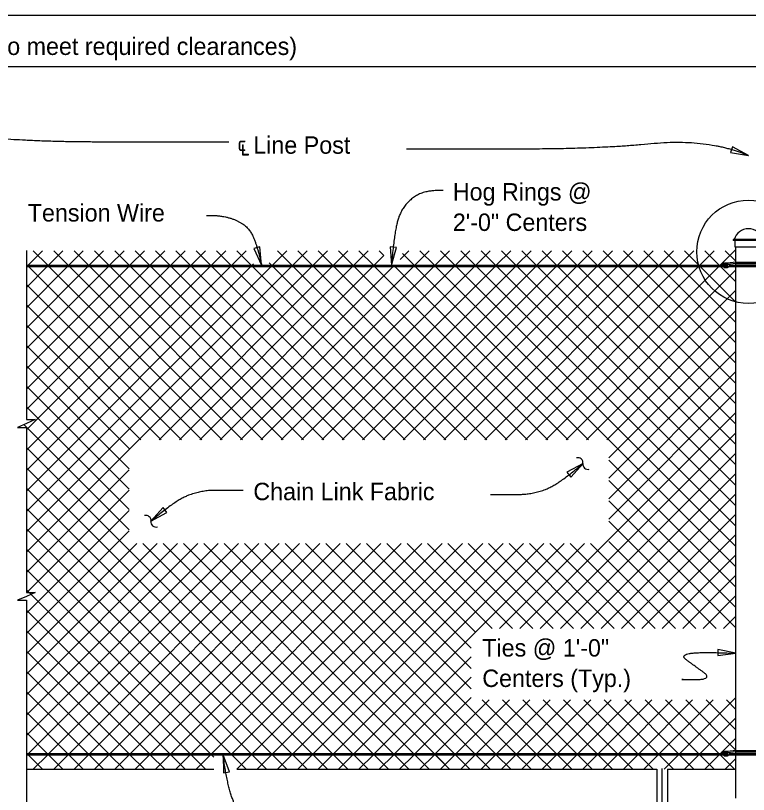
# Model space of a CAD drawing. Extents: x 0 to 72.1, y -15.2 to 30.1.
# Drawn here: x 16.14 to 24.63, y 18.99 to 28 of the extents above; entities that cross this region are included whole.
import ezdxf

# ---------------------------------------------------------------- set-up
doc = ezdxf.new("R2010")
doc.units = 0
for name, color, linetype in [('ActivePts-ConstElements', 7, 'Continuous'), ('AdhocPoint_dp', 7, 'Continuous'), ('Border', 7, 'Continuous'), ('Patterning', 7, 'Continuous'), ('PlotBorder_dp', 7, 'Continuous'), ('SheetBorder_dp', 7, 'Continuous'), ('SheetLines_dp', 7, 'Continuous'), ('TextMisc', 7, 'Continuous')]:
    doc.layers.add(name, color=color, linetype=linetype)

msp = doc.modelspace()

# ---------------------------------------------------------------- linework, layer by layer
at = {"layer": 'ActivePts-ConstElements'}
msp.add_lwpolyline([(0.016, 2.0538), (41.0666, 2.0538), (41.0666, 27.9999), (0.016, 27.9999)], close=True, dxfattribs=at)
at = {"layer": 'AdhocPoint_dp'}
for p, q in [((16.268, 19.2783), (18.44, 19.2783)), ((18.704, 19.2783), (23.5698, 19.2783)), ((23.5698, 19.2783), (23.5698, 14.757)), ((23.6923, 19.2783), (23.6923, 15.6116)), ((23.6923, 19.2783), (24.4852, 19.2783))]:
    msp.add_line(p, q, dxfattribs=at)
at = {"layer": 'Border'}
for p, q in [((24.4852, 25.1116), (24.7769, 25.1116)), ((24.4852, 25.0969), (24.7769, 25.0969)), ((24.4852, 19.4597), (24.7769, 19.4597)), ((24.4852, 19.445), (24.7769, 19.445))]:
    msp.add_line(p, q, dxfattribs=at)
at = {"layer": 'Patterning'}
for p, q in [((16.2896, 25.1116), (16.4562, 25.2783)), ((16.3488, 25.2783), (16.5155, 25.1116)), ((16.5253, 25.1116), (16.6919, 25.2783)), ((16.5845, 25.2783), (16.7512, 25.1116)), ((16.761, 25.1116), (16.9276, 25.2783)), ((16.8202, 25.2783), (16.9869, 25.1116)), ((16.9967, 25.1116), (17.1633, 25.2783)), ((17.0559, 25.2783), (17.2226, 25.1116)), ((17.2324, 25.1116), (17.3991, 25.2783)), ((17.2916, 25.2783), (17.4583, 25.1116)), ((17.4681, 25.1116), (17.6348, 25.2783)), ((17.5273, 25.2783), (17.694, 25.1116)), ((17.7038, 25.1116), (17.8705, 25.2783)), ((17.763, 25.2783), (17.9297, 25.1116)), ((17.9395, 25.1116), (18.1062, 25.2783)), ((17.9987, 25.2783), (18.1654, 25.1116)), ((18.1752, 25.1116), (18.3419, 25.2783)), ((18.2344, 25.2783), (18.4011, 25.1116)), ((18.4109, 25.1116), (18.5776, 25.2783)), ((18.4701, 25.2783), (18.6368, 25.1116)), ((18.6466, 25.1116), (18.8133, 25.2783)), ((18.7058, 25.2783), (18.8725, 25.1116)), ((19.118, 25.1116), (19.2847, 25.2783)), ((19.1772, 25.2783), (19.3439, 25.1116)), ((19.3537, 25.1116), (19.5204, 25.2783)), ((19.4129, 25.2783), (19.5796, 25.1116)), ((19.5894, 25.1116), (19.7561, 25.2783)), ((19.6486, 25.2783), (19.8153, 25.1116)), ((19.8251, 25.1116), (19.9918, 25.2783)), ((19.8843, 25.2783), (20.051, 25.1116)), ((20.0608, 25.1116), (20.2275, 25.2783)), ((20.12, 25.2783), (20.2867, 25.1116)), ((20.3557, 25.2783), (20.4095, 25.2246)), ((20.5989, 25.1783), (20.6989, 25.2783)), ((20.6246, 25.2452), (20.7581, 25.1116)), ((20.7679, 25.1116), (20.9346, 25.2783)), ((20.8271, 25.2783), (20.9938, 25.1116)), ((21.0036, 25.1116), (21.1703, 25.2783)), ((21.0628, 25.2783), (21.2295, 25.1116)), ((21.2393, 25.1116), (21.406, 25.2783)), ((21.2985, 25.2783), (21.4652, 25.1116)), ((21.475, 25.1116), (21.6417, 25.2783)), ((21.5342, 25.2783), (21.7009, 25.1116)), ((21.7107, 25.1116), (21.8774, 25.2783)), ((21.7699, 25.2783), (21.9366, 25.1116)), ((21.9464, 25.1116), (22.1131, 25.2783)), ((22.0057, 25.2783), (22.1723, 25.1116)), ((22.1821, 25.1116), (22.3488, 25.2783)), ((22.2414, 25.2783), (22.408, 25.1116)), ((22.2834, 23.0916), (24.4852, 25.2934)), ((22.4178, 25.1116), (22.5845, 25.2783)), ((22.4771, 25.2783), (22.6437, 25.1116)), ((22.6535, 25.1116), (22.8202, 25.2783)), ((22.7128, 25.2783), (22.8794, 25.1116)), ((22.8892, 25.1116), (23.0559, 25.2783)), ((22.9485, 25.2783), (23.1151, 25.1116)), ((23.1249, 25.1116), (23.2916, 25.2783)), ((23.1842, 25.2783), (23.3508, 25.1116)), ((23.3606, 25.1116), (23.5273, 25.2783)), ((23.4199, 25.2783), (23.5865, 25.1116)), ((23.5963, 25.1116), (23.763, 25.2783)), ((23.6556, 25.2783), (23.8222, 25.1116)), ((23.832, 25.1116), (23.9987, 25.2783)), ((23.8913, 25.2783), (24.0579, 25.1116)), ((24.0677, 25.1116), (24.2344, 25.2783)), ((24.127, 25.2783), (24.2936, 25.1116)), ((24.3035, 25.1116), (24.4701, 25.2783)), ((24.3627, 25.2783), (24.4852, 25.1557)), ((20.2965, 25.1116), (20.4095, 25.2246)), ((16.268, 21.7902), (19.5747, 25.0969)), ((16.268, 22.2616), (19.1033, 25.0969)), ((16.268, 23.2044), (18.1604, 25.0969)), ((16.268, 22.733), (18.6318, 25.0969)), ((16.268, 22.0259), (19.339, 25.0969)), ((16.268, 22.4973), (18.8675, 25.0969)), ((16.268, 22.9687), (18.3961, 25.0969)), ((16.268, 23.4402), (17.9247, 25.0969)), ((16.268, 23.6759), (17.689, 25.0969)), ((16.268, 24.1473), (17.2176, 25.0969)), ((16.268, 23.9116), (17.4533, 25.0969)), ((16.268, 24.6187), (16.7462, 25.0969)), ((16.268, 25.0901), (16.2748, 25.0969)), ((16.268, 24.383), (16.9819, 25.0969)), ((16.268, 24.8544), (16.5105, 25.0969)), ((16.2945, 25.0969), (18.2998, 23.0916)), ((16.5302, 25.0969), (18.5355, 23.0916)), ((16.7659, 25.0969), (18.7712, 23.0916)), ((17.0016, 25.0969), (19.0069, 23.0916)), ((17.2373, 25.0969), (19.2426, 23.0916)), ((17.473, 25.0969), (19.4783, 23.0916)), ((17.7087, 25.0969), (19.714, 23.0916)), ((17.8051, 23.0916), (19.8104, 25.0969)), ((17.9444, 25.0969), (19.9497, 23.0916)), ((18.0408, 23.0916), (20.0461, 25.0969)), ((18.1801, 25.0969), (20.1854, 23.0916)), ((18.2765, 23.0916), (20.2818, 25.0969)), ((18.4158, 25.0969), (20.4211, 23.0916)), ((18.5122, 23.0916), (20.5175, 25.0969)), ((18.6515, 25.0969), (20.6568, 23.0916)), ((18.7479, 23.0916), (20.7532, 25.0969)), ((18.8823, 25.1116), (18.8973, 25.1266)), ((18.8872, 25.0969), (20.8925, 23.0916)), ((18.9836, 23.0916), (20.9889, 25.0969)), ((19.081, 25.1388), (19.1082, 25.1116)), ((19.1229, 25.0969), (21.1282, 23.0916)), ((19.2193, 23.0916), (21.2246, 25.0969)), ((19.3586, 25.0969), (21.3639, 23.0916)), ((19.455, 23.0916), (21.4603, 25.0969)), ((19.5943, 25.0969), (21.5996, 23.0916)), ((19.6907, 23.0916), (21.696, 25.0969)), ((19.83, 25.0969), (21.8353, 23.0916)), ((19.9264, 23.0916), (21.9317, 25.0969)), ((20.0657, 25.0969), (22.071, 23.0916)), ((20.1621, 23.0916), (22.1674, 25.0969)), ((20.3015, 25.0969), (22.3067, 23.0916)), ((20.3978, 23.0916), (22.4031, 25.0969)), ((20.5372, 25.0969), (22.5424, 23.0916)), ((20.6335, 23.0916), (22.6388, 25.0969)), ((20.7729, 25.0969), (22.7781, 23.0916)), ((20.8692, 23.0916), (22.8745, 25.0969)), ((21.0086, 25.0969), (24.4852, 21.6202)), ((21.1049, 23.0916), (23.1102, 25.0969)), ((21.2443, 25.0969), (24.4852, 21.8559)), ((21.3406, 23.0916), (23.3459, 25.0969)), ((21.48, 25.0969), (24.4852, 22.0916)), ((21.5763, 23.0916), (23.5816, 25.0969)), ((21.7157, 25.0969), (24.4852, 22.3273)), ((21.812, 23.0916), (23.8173, 25.0969)), ((21.9514, 25.0969), (24.4852, 22.563)), ((22.0477, 23.0916), (24.053, 25.0969)), ((22.1871, 25.0969), (24.4852, 22.7987)), ((22.4228, 25.0969), (24.4852, 23.0344)), ((22.6585, 25.0969), (24.4852, 23.2701)), ((22.8942, 25.0969), (24.4852, 23.5058)), ((23.1299, 25.0969), (24.4852, 23.7415)), ((23.3656, 25.0969), (24.4852, 23.9772)), ((23.6013, 25.0969), (24.4852, 24.2129)), ((23.837, 25.0969), (24.4852, 24.4486)), ((24.0727, 25.0969), (24.4852, 24.6843)), ((24.3084, 25.0969), (24.4852, 24.92)), ((22.5191, 23.0916), (24.4852, 25.0577)), ((16.268, 24.8877), (18.0641, 23.0916)), ((22.7548, 23.0916), (24.4852, 24.822)), ((16.268, 24.652), (17.8284, 23.0916)), ((22.9905, 23.0916), (24.4852, 24.5863)), ((16.268, 24.4163), (17.5927, 23.0916)), ((23.0145, 22.8799), (24.4852, 24.3506)), ((16.268, 24.1806), (17.4577, 22.9909)), ((23.0145, 22.6442), (24.4852, 24.1149)), ((16.268, 23.9449), (17.4577, 22.7552)), ((23.0145, 22.4085), (24.4852, 23.8792)), ((16.268, 23.7092), (17.4577, 22.5195)), ((23.0145, 22.1728), (24.4852, 23.6435)), ((16.268, 23.4735), (17.4577, 22.2838)), ((21.9837, 20.9063), (24.4852, 23.4078)), ((16.2393, 23.2665), (17.4577, 22.0481)), ((22.2194, 20.9063), (24.4852, 23.1721)), ((16.268, 23.0021), (19.8104, 19.4597)), ((22.4551, 20.9063), (24.4852, 22.9364)), ((23.0145, 22.8552), (24.4852, 21.3845)), ((16.268, 22.7664), (19.5747, 19.4597)), ((16.268, 21.5545), (17.4577, 22.7442)), ((22.6908, 20.9063), (24.4852, 22.7007)), ((23.0145, 22.6195), (24.4852, 21.1488)), ((16.268, 22.5307), (19.339, 19.4597)), ((16.2718, 21.3227), (17.4577, 22.5085)), ((22.9265, 20.9063), (24.4852, 22.465)), ((23.0145, 22.3838), (24.4852, 20.9131)), ((16.268, 22.295), (19.1033, 19.4597)), ((16.268, 21.0831), (17.4577, 22.2728)), ((23.1623, 20.9063), (24.4852, 22.2293)), ((23.0145, 22.1481), (24.2563, 20.9063)), ((16.268, 22.0593), (18.8675, 19.4597)), ((16.268, 20.8474), (17.4577, 22.0371)), ((23.0145, 21.9124), (24.0206, 20.9063)), ((23.398, 20.9063), (24.4852, 21.9936)), ((16.268, 19.9046), (18.2538, 21.8904)), ((16.268, 20.376), (17.7824, 21.8904)), ((16.268, 20.6117), (17.5467, 21.8904)), ((16.268, 20.1403), (18.0181, 21.8904)), ((16.268, 19.6689), (18.4895, 21.8904)), ((16.268, 21.8236), (18.6318, 19.4597)), ((16.2945, 19.4597), (18.7252, 21.8904)), ((16.5302, 19.4597), (18.9609, 21.8904)), ((16.7659, 19.4597), (19.1966, 21.8904)), ((17.0016, 19.4597), (19.4323, 21.8904)), ((17.2373, 19.4597), (19.668, 21.8904)), ((17.473, 19.4597), (19.9037, 21.8904)), ((17.6154, 21.8904), (20.0461, 19.4597)), ((17.7087, 19.4597), (20.1394, 21.8904)), ((17.8511, 21.8904), (20.2818, 19.4597)), ((17.9444, 19.4597), (20.3751, 21.8904)), ((18.0868, 21.8904), (20.5175, 19.4597)), ((18.1801, 19.4597), (20.6108, 21.8904)), ((18.3225, 21.8904), (20.7532, 19.4597)), ((18.4158, 19.4597), (20.8465, 21.8904)), ((18.5582, 21.8904), (21.1067, 19.3419)), ((18.6515, 19.4597), (21.0822, 21.8904)), ((18.7939, 21.8904), (21.2246, 19.4597)), ((18.8872, 19.4597), (21.3179, 21.8904)), ((19.0296, 21.8904), (21.4603, 19.4597)), ((19.1229, 19.4597), (21.5536, 21.8904)), ((19.2653, 21.8904), (21.696, 19.4597)), ((19.3586, 19.4597), (21.7893, 21.8904)), ((19.501, 21.8904), (21.9317, 19.4597)), ((19.5943, 19.4597), (22.025, 21.8904)), ((19.7122, 19.3419), (22.2607, 21.8904)), ((19.7367, 21.8904), (21.42, 20.2072)), ((19.9724, 21.8904), (21.42, 20.4429)), ((20.0657, 19.4597), (22.4964, 21.8904)), ((20.2081, 21.8904), (21.42, 20.6786)), ((20.4438, 21.8904), (21.4701, 20.8641)), ((20.6795, 21.8904), (21.6636, 20.9063)), ((20.9152, 21.8904), (21.8993, 20.9063)), ((21.1509, 21.8904), (22.135, 20.9063)), ((21.3866, 21.8904), (22.3707, 20.9063)), ((21.6223, 21.8904), (22.6064, 20.9063)), ((21.748, 20.9063), (22.7321, 21.8904)), ((21.858, 21.8904), (22.8421, 20.9063)), ((22.0937, 21.8904), (23.0778, 20.9063)), ((22.3294, 21.8904), (23.3135, 20.9063)), ((22.5651, 21.8904), (23.5492, 20.9063)), ((22.8008, 21.8904), (23.7849, 20.9063)), ((23.6337, 20.9063), (24.4852, 21.7579)), ((16.268, 21.5879), (18.3961, 19.4597)), ((23.8694, 20.9063), (24.4852, 21.5222)), ((16.268, 21.3522), (18.1604, 19.4597)), ((24.1051, 20.9063), (24.4852, 21.2865)), ((16.268, 21.1165), (17.9247, 19.4597)), ((24.3408, 20.9063), (24.4852, 21.0508)), ((16.268, 20.8808), (17.689, 19.4597)), ((16.268, 20.6451), (17.4533, 19.4597)), ((20.3015, 19.4597), (21.42, 20.5782)), ((16.268, 20.4094), (17.2176, 19.4597)), ((20.5372, 19.4597), (21.42, 20.3425)), ((16.268, 20.1737), (16.9819, 19.4597)), ((20.7729, 19.4597), (21.42, 20.1068)), ((23.837, 19.4597), (24.4852, 20.108)), ((21.0086, 19.4597), (21.6282, 20.0793)), ((21.2443, 19.4597), (21.8639, 20.0793)), ((21.48, 19.4597), (22.0996, 20.0793)), ((21.5478, 20.0793), (22.1674, 19.4597)), ((21.7157, 19.4597), (22.3353, 20.0793)), ((21.7835, 20.0793), (22.4031, 19.4597)), ((21.9514, 19.4597), (22.571, 20.0793)), ((22.0192, 20.0793), (22.6388, 19.4597)), ((22.1871, 19.4597), (22.8067, 20.0793)), ((22.2549, 20.0793), (22.8745, 19.4597)), ((22.4228, 19.4597), (23.0424, 20.0793)), ((22.4906, 20.0793), (23.1102, 19.4597)), ((22.6585, 19.4597), (23.2781, 20.0793)), ((22.7263, 20.0793), (23.3459, 19.4597)), ((22.8942, 19.4597), (23.5138, 20.0793)), ((22.962, 20.0793), (23.5816, 19.4597)), ((23.1299, 19.4597), (23.7495, 20.0793)), ((23.1977, 20.0793), (23.8173, 19.4597)), ((23.3656, 19.4597), (23.9852, 20.0793)), ((23.4334, 20.0793), (24.053, 19.4597)), ((23.6013, 19.4597), (24.2209, 20.0793)), ((23.6691, 20.0793), (24.2887, 19.4597)), ((23.9048, 20.0793), (24.4852, 19.4989)), ((24.1405, 20.0793), (24.4852, 19.7346)), ((24.3762, 20.0793), (24.4852, 19.9703)), ((16.268, 19.938), (16.7462, 19.4597)), ((24.0727, 19.4597), (24.4852, 19.8723)), ((16.268, 19.7023), (16.5105, 19.4597)), ((24.3243, 19.4757), (24.4852, 19.6366)), ((16.2896, 19.445), (16.4562, 19.2783)), ((16.3488, 19.2783), (16.5155, 19.445)), ((16.5253, 19.445), (16.6919, 19.2783)), ((16.5845, 19.2783), (16.7512, 19.445)), ((16.761, 19.445), (16.9276, 19.2783)), ((16.8202, 19.2783), (16.9869, 19.445)), ((16.9967, 19.445), (17.1633, 19.2783)), ((17.0559, 19.2783), (17.2226, 19.445)), ((17.2324, 19.445), (17.3991, 19.2783)), ((17.2916, 19.2783), (17.4583, 19.445)), ((17.4681, 19.445), (17.6348, 19.2783)), ((17.5273, 19.2783), (17.694, 19.445)), ((17.7038, 19.445), (17.8705, 19.2783)), ((17.763, 19.2783), (17.9297, 19.445)), ((17.9395, 19.445), (18.1062, 19.2783)), ((17.9987, 19.2783), (18.1654, 19.445)), ((18.1752, 19.445), (18.3419, 19.2783)), ((18.2344, 19.2783), (18.4011, 19.445)), ((18.4109, 19.445), (18.44, 19.4159)), ((18.6466, 19.445), (18.8133, 19.2783)), ((18.7058, 19.2783), (18.8725, 19.445)), ((18.8823, 19.445), (19.049, 19.2783)), ((18.9415, 19.2783), (19.1082, 19.445)), ((19.118, 19.445), (19.2847, 19.2783)), ((19.1772, 19.2783), (19.3439, 19.445)), ((19.3537, 19.445), (19.5204, 19.2783)), ((19.4129, 19.2783), (19.5796, 19.445)), ((19.5894, 19.445), (19.7561, 19.2783)), ((19.6486, 19.2783), (19.8153, 19.445)), ((19.8251, 19.445), (19.9918, 19.2783)), ((19.8843, 19.2783), (20.051, 19.445)), ((20.0608, 19.445), (20.2275, 19.2783)), ((20.12, 19.2783), (20.2867, 19.445)), ((20.2965, 19.445), (20.4632, 19.2783)), ((20.3557, 19.2783), (20.5224, 19.445)), ((20.5322, 19.445), (20.6989, 19.2783)), ((20.5914, 19.2783), (20.7581, 19.445)), ((20.7679, 19.445), (20.9346, 19.2783)), ((20.8271, 19.2783), (20.9938, 19.445)), ((21.0036, 19.445), (21.1703, 19.2783)), ((21.0628, 19.2783), (21.2295, 19.445)), ((21.2393, 19.445), (21.406, 19.2783)), ((21.2985, 19.2783), (21.4652, 19.445)), ((21.475, 19.445), (21.6417, 19.2783)), ((21.5342, 19.2783), (21.7009, 19.445)), ((21.7107, 19.445), (21.8774, 19.2783)), ((21.7699, 19.2783), (21.9366, 19.445)), ((21.9464, 19.445), (22.1131, 19.2783)), ((22.0057, 19.2783), (22.1723, 19.445)), ((22.1821, 19.445), (22.3488, 19.2783)), ((22.2414, 19.2783), (22.408, 19.445)), ((22.4178, 19.445), (22.5845, 19.2783)), ((22.4771, 19.2783), (22.6437, 19.445)), ((22.6535, 19.445), (22.8202, 19.2783)), ((22.7128, 19.2783), (22.8794, 19.445)), ((22.8892, 19.445), (23.0559, 19.2783)), ((22.9485, 19.2783), (23.1151, 19.445)), ((23.1249, 19.445), (23.2916, 19.2783)), ((23.1842, 19.2783), (23.3508, 19.445)), ((23.3606, 19.445), (23.5273, 19.2783)), ((23.4199, 19.2783), (23.5865, 19.445)), ((23.5963, 19.445), (23.763, 19.2783)), ((23.6556, 19.2783), (23.8222, 19.445)), ((23.832, 19.445), (23.9987, 19.2783)), ((23.8913, 19.2783), (24.0579, 19.445)), ((24.0677, 19.445), (24.2344, 19.2783)), ((24.127, 19.2783), (24.2936, 19.445)), ((24.3035, 19.445), (24.4701, 19.2783)), ((24.3084, 19.4597), (24.312, 19.4633)), ((24.3627, 19.2783), (24.4852, 19.4009))]:
    msp.add_line(p, q, dxfattribs=at)
at = {"layer": 'PlotBorder_dp'}
for points in [[(13.631, 27.4094), (15.0947, 27.4094), (15.0947, 27.5128), (15.1397, 27.4094), (15.1847, 27.3061), (15.1847, 27.4094), (28.4756, 27.4094)], [(16.268, 25.2804), (16.268, 23.3241), (16.3714, 23.3241), (16.268, 23.2791), (16.1647, 23.2341), (16.268, 23.2341), (16.268, 22.3405)], [(16.268, 22.3405), (16.268, 21.3227), (16.3714, 21.3227), (16.268, 21.2777), (16.1647, 21.2327), (16.268, 21.2327), (16.268, 19.0284)], [(16.268, 19.2784), (16.268, 17.4276), (16.3714, 17.4276), (16.268, 17.3826), (16.1647, 17.3376), (16.268, 17.3376), (16.268, 14.9877)]]:
    msp.add_lwpolyline(points, dxfattribs=at)
for points in [[(24.6311, 26.3822), (24.4447, 26.4815), (24.4224, 26.4146)], [(18.9924, 25.1117), (18.9722, 25.3219), (18.9041, 25.3035)], [(20.4977, 25.1117), (20.5537, 25.3153), (20.4835, 25.3224)], [(22.7151, 22.8151), (22.5295, 22.7141), (22.5731, 22.6586)], [(17.711, 22.1484), (17.8965, 22.2494), (17.8529, 22.3049)], [(24.4853, 20.6199), (24.2786, 20.6637), (24.2757, 20.5932)], [(18.5457, 19.445), (18.5507, 19.2338), (18.6199, 19.2473)]]:
    msp.add_lwpolyline(points, close=True, dxfattribs=at)
msp.add_circle((24.631, 25.2659), 0.5976, dxfattribs=at)
for centre, start, end in [((22.6555, 22.8235), 352.34263, 104.06985), ((22.7736, 22.8076), 172.34263, 284.06985), ((17.6524, 22.1558), 352.34263, 104.06985), ((17.7706, 22.1399), 172.34263, 284.06985)]:
    msp.add_arc(centre, 0.0596, start, end, dxfattribs=at)
for points in [[(18.6126, 26.5365), (17.8093, 26.5365), (16.42, 26.5365), (15.2385, 26.6311), (14.631, 26.7352)], [(20.6722, 26.4584), (21.1189, 26.4584), (22.8863, 26.4584), (24.1529, 26.5814), (24.631, 26.3821)], [(21.0973, 25.9736), (20.8794, 25.986), (20.6356, 25.8115), (20.5295, 25.5276), (20.4977, 25.1116)], [(18.354, 25.687), (18.5344, 25.6941), (18.8173, 25.5843), (18.9376, 25.3648), (18.9924, 25.1116)], [(21.6418, 22.4586), (21.8439, 22.4586), (22.1175, 22.4586), (22.4243, 22.5665), (22.7145, 22.8155)], [(18.7799, 22.5048), (18.5821, 22.5048), (18.3085, 22.5048), (18.0018, 22.3969), (17.7116, 22.148)], [(23.8747, 20.3153), (23.8093, 20.3153), (24.2294, 20.3153), (23.9791, 20.4924), (23.842, 20.5951), (24.0525, 20.6376), (24.4853, 20.6199)], [(19.2088, 18.651), (18.8109, 18.651), (18.6069, 18.988), (18.5457, 19.4449)]]:
    msp.add_open_spline(points, degree=2, dxfattribs=at)
at = {"layer": 'SheetBorder_dp'}
msp.add_line((23.6311, 13.3896), (23.6311, 19.2851), dxfattribs=at)
at = {"layer": 'TextMisc'}
for p, q in [((24.4587, 25.4103), (24.8033, 25.4103)), ((24.8033, 25.398), (24.4587, 25.398)), ((24.477, 25.3183), (24.477, 25.398)), ((24.7851, 25.3183), (24.477, 25.3183)), ((24.4852, 18.9432), (24.4852, 25.3183)), ((16.268, 25.1116), (24.3101, 25.1116)), ((16.268, 25.0969), (24.3367, 25.0969)), ((24.32, 25.1116), (24.3332, 25.1116)), ((24.4852, 25.1443), (24.3904, 25.1332)), ((24.4852, 25.1297), (24.3926, 25.1202)), ((24.4016, 25.0969), (24.4852, 25.0969)), ((24.4031, 25.1116), (24.4852, 25.1116)), ((24.4852, 25.1443), (24.7764, 25.1459)), ((24.4852, 25.1297), (24.7764, 25.1314)), ((24.4852, 19.4923), (24.3904, 19.4812)), ((24.4852, 19.4778), (24.3926, 19.4683)), ((24.4852, 19.4923), (24.7764, 19.494)), ((24.4852, 19.4778), (24.7764, 19.4795)), ((16.268, 19.4597), (24.3101, 19.4597)), ((16.268, 19.445), (24.3367, 19.445)), ((24.32, 19.4597), (24.3332, 19.4597)), ((24.4016, 19.445), (24.4852, 19.445)), ((24.4031, 19.4597), (24.4852, 19.4597))]:
    msp.add_line(p, q, dxfattribs=at)
msp.add_arc((24.4589, 25.404), 0.00613, 91.1647, 268.8353, dxfattribs=at)
for centre, major_axis, ratio, start_param, end_param in [((24.6317, 25.3692), (0.1711, 0), 0.957868, 0.252602, 2.888574), ((24.3443, 25.0974), (0.0373, 0), 0.957868, 1.486836, 3.108042), ((24.3654, 25.0577), (-0.0724, 0), 0.957868, 5.162149, 5.652106), ((24.358, 25.1093), (-0.0249, 0), 0.957868, 6.009018, 7.089857), ((24.3568, 25.1119), (0.023, 0), 0.957868, 1.29026, 2.970541), ((24.3593, 25.1053), (0.0231, 0), 0.957868, 3.779554, 4.879821), ((24.3756, 25.1065), (0.0295, 0), 0.957868, 1.220941, 4.039556), ((24.389, 25.1083), (-0.0303, -0.0108), 0.724765, 4.35367, 6.324556), ((24.3654, 25.0997), (0.0206, -0.0021), 0.798607, 4.32653, 5.220153), ((24.3789, 25.0997), (0.0206, -0.0021), 0.798607, 3.333154, 5.220153), ((24.3857, 25.1042), (-0.0139, 0), 0.957868, 5.22362, 6.905413), ((24.3801, 25.1018), (-0.00795, 0), 0.957868, 6.140374, 9.314262), ((24.3941, 25.0953), (-0.0259, 0), 0.957868, 4.777514, 5.62749), ((24.3784, 25.1076), (0.0119, 0), 0.957868, 5.725876, 7.416677), ((24.3715, 25.1184), (0.0391, 0), 0.957868, 5.082588, 5.41974), ((24.3784, 25.1076), (0.0119, 0), 0.957868, 5.639684, 5.723117), ((24.3786, 25.1064), (0.0251, 0), 0.957868, 5.531357, 6.227833), ((24.3786, 25.1064), (0.0251, 0), 0.957868, 0.407687, 0.609214), ((24.3443, 19.4455), (0.0373, 0), 0.957868, 1.486836, 3.108042), ((24.3568, 19.4599), (0.023, 0), 0.957868, 1.29026, 2.970541), ((24.3756, 19.4546), (0.0295, 0), 0.957868, 1.220941, 4.039556), ((24.389, 19.4563), (-0.0303, -0.0108), 0.724765, 4.35367, 6.324556), ((24.3654, 19.4058), (-0.0724, 0), 0.957868, 5.162149, 5.652106), ((24.358, 19.4574), (-0.0249, 0), 0.957868, 6.009018, 7.089857), ((24.3593, 19.4534), (0.0231, 0), 0.957868, 3.779554, 4.879821), ((24.3654, 19.4477), (0.0206, -0.0021), 0.798607, 4.32653, 5.220153), ((24.3789, 19.4477), (0.0206, -0.0021), 0.798607, 3.333154, 5.220153), ((24.3857, 19.4523), (-0.0139, 0), 0.957868, 5.22362, 6.905413), ((24.3801, 19.4499), (-0.00795, 0), 0.957868, 6.140374, 9.314262), ((24.3941, 19.4434), (-0.0259, 0), 0.957868, 4.777514, 5.62749), ((24.3784, 19.4557), (0.0119, 0), 0.957868, 5.725876, 7.416677), ((24.3715, 19.4665), (0.0391, 0), 0.957868, 5.082588, 5.41974), ((24.3784, 19.4557), (0.0119, 0), 0.957868, 5.639684, 5.723117), ((24.3786, 19.4544), (0.0251, 0), 0.957868, 5.531357, 6.227833), ((24.3786, 19.4544), (0.0251, 0), 0.957868, 0.407687, 0.609214)]:
    msp.add_ellipse(centre, major_axis=major_axis, ratio=ratio, start_param=start_param, end_param=end_param, dxfattribs=at)

# ---------------------------------------------------------------- texts
at = {"layer": 'PlotBorder_dp'}
for s, p in [('Hog Rings @ ', (21.2071, 25.8593)), ('2\'-0" Centers', (21.2071, 25.5073)), ('Ties @ 1\'-0" ', (21.5486, 20.5813)), ('Centers (Typ.)', (21.5486, 20.2293))]:
    msp.add_text(s, height=0.2016, dxfattribs=at).set_placement(p)
at = {"layer": 'SheetLines_dp'}
for s, p in [('Equal Spaces @ 10\'-0" Max. (Posts may be shifted minimally to meet required clearances)', (8.5986, 27.544)), ('℄ Line Post', (18.7118, 26.4008)), ('Tension Wire', (16.284, 25.6165)), ('Chain Link Fabric', (18.8971, 22.3912))]:
    msp.add_text(s, height=0.2016, dxfattribs=at).set_placement(p)

doc.saveas('drawing.dxf')
